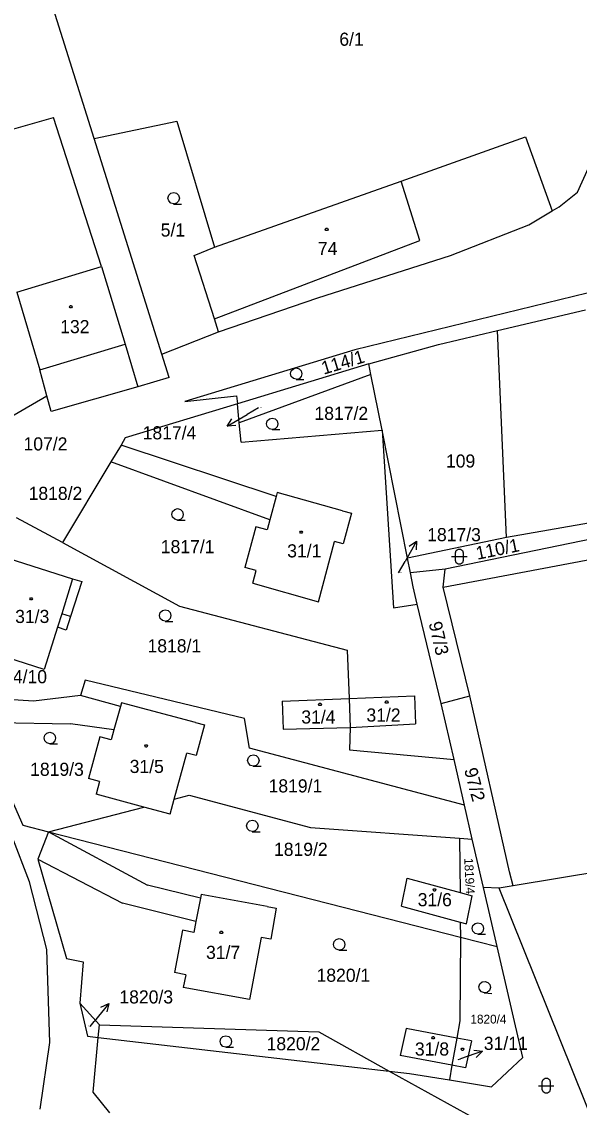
# Model space of a CAD drawing. Extents: x -799786 to -795190, y -1021716 to -1017834.
# Drawn here: x -797930.9 to -797858.7, y -1019054.3 to -1018913.6 of the extents above; entities that cross this region are included whole.
import ezdxf

# ---------------------------------------------------------------- set-up
doc = ezdxf.new("R2010")
doc.units = 0
for name, color, linetype in [('Default', 7, 'Continuous'), ('KN_HRANICE', 7, 'Continuous'), ('KN_KULTURY', 7, 'Continuous'), ('KN_PARCELY', 7, 'Continuous'), ('KN_SLUCKY', 7, 'Continuous')]:
    doc.layers.add(name, color=color, linetype=linetype)

# ---------------------------------------------------------------- blocks, each defined once
blk = doc.blocks.new('304')
at = {"layer": 'Default'}
blk.add_lwpolyline([(0, 0), (-0.38, 0.1), (-0.65, 0.37), (-0.75, 0.74), (-0.65, 1.11), (-0.38, 1.38), (-0.01, 1.48), (0.36, 1.38), (0.63, 1.11), (0.73, 0.73), (0.63, 0.35), (0.36, 0.08), (-0.02, -0.02), (0.98, -0.02)], dxfattribs=at)
blk = doc.blocks.new('316')
at = {"layer": 'Default'}
for points in [[(-0.5, 1.5), (-0.4, 1.79), (-0.15, 1.97), (0.16, 1.97), (0.41, 1.79), (0.51, 1.5), (0.51, 0.5), (0.41, 0.21), (0.16, 0.03), (-0.15, 0.03), (-0.4, 0.21), (-0.5, 0.5), (-0.5, 1.5)], [(-1, 1), (0.27, 1), (1, 1)]]:
    blk.add_lwpolyline(points, dxfattribs=at)
blk = doc.blocks.new('10292')
at = {"layer": 'Default'}
blk.add_line((0, 3), (0, 0), dxfattribs=at)
blk.add_lwpolyline([(-0.5, 2), (0, 3), (0.5, 2)], dxfattribs=at)
blk = doc.blocks.new('402')
at = {"layer": 'Default'}
blk.add_lwpolyline([(0.09, 0.15), (0.18, 0), (0.09, -0.15), (-0.09, -0.15), (-0.18, 0), (-0.09, 0.15), (0.09, 0.15)], dxfattribs=at)

msp = doc.modelspace()

# ---------------------------------------------------------------- linework, layer by layer
at = {"layer": 'KN_HRANICE'}
for p, q in [((-797921.5, -1018928.71), (-797931.74, -1018896.06)), ((-797936.24, -1018928.69), (-797926.78, -1018925.98)), ((-797920.53, -1018945.32), (-797926.78, -1018925.98)), ((-797921.5, -1018928.71), (-797910.8, -1018926.48)), ((-797910.8, -1018926.48), (-797905.9, -1018942.82)), ((-797912.72, -1018956.68), (-797921.5, -1018928.71)), ((-797881.76, -1018934.25), (-797865.66, -1018928.52)), ((-797865.66, -1018928.52), (-797862.2, -1018938.11)), ((-797858.91, -1018935.69), (-797856.04, -1018929.36)), ((-797905.9, -1018942.82), (-797881.76, -1018934.25)), ((-797908.54, -1018943.89), (-797905.9, -1018942.82)), ((-797905.93, -1018952.07), (-797908.54, -1018943.89)), ((-797920.53, -1018945.32), (-797917.5, -1018955.39)), ((-797931.53, -1018948.65), (-797928.55, -1018958.72)), ((-797855.89, -1018948.34), (-797887.74, -1018956.13)), ((-797869.28, -1018953.62), (-797857.87, -1018950.94)), ((-797905.4, -1018953.76), (-797905.93, -1018952.07)), ((-797912.72, -1018956.68), (-797905.4, -1018953.76)), ((-797876.92, -1018955.41), (-797869.28, -1018953.62)), ((-797868.08, -1018980.41), (-797869.28, -1018953.62)), ((-797917.5, -1018955.39), (-797915.84, -1018960.89)), ((-797887.74, -1018956.13), (-797909.74, -1018962.8)), ((-797885.92, -1018957.93), (-797876.92, -1018955.41)), ((-797911.78, -1018959.68), (-797912.72, -1018956.68)), ((-797927.62, -1018962.07), (-797928.55, -1018958.72)), ((-797885.92, -1018957.93), (-797902.94, -1018963.09)), ((-797885.65, -1018959.3), (-797885.92, -1018957.93)), ((-797911.78, -1018959.68), (-797915.84, -1018960.89)), ((-797885.65, -1018959.3), (-797902.7, -1018965.57)), ((-797884.22, -1018966.52), (-797885.65, -1018959.3)), ((-797915.84, -1018960.89), (-797927.05, -1018964.12)), ((-797935.14, -1018966.41), (-797927.62, -1018962.07)), ((-797927.05, -1018964.12), (-797927.62, -1018962.07)), ((-797902.94, -1018963.09), (-797917.5, -1018967.51)), ((-797909.74, -1018962.8), (-797903.08, -1018962.08)), ((-797903.08, -1018962.08), (-797902.94, -1018963.09)), ((-797902.7, -1018965.57), (-797902.94, -1018963.09)), ((-797902.45, -1018968.07), (-797902.7, -1018965.57)), ((-797902.45, -1018968.07), (-797884.22, -1018966.52)), ((-797884.22, -1018966.52), (-797882.75, -1018989.54)), ((-797880.92, -1018983.12), (-797884.22, -1018966.52)), ((-797917.99, -1018968.46), (-797919.35, -1018970.64)), ((-797917.5, -1018967.51), (-797917.99, -1018968.46)), ((-797897.94, -1018975.1), (-797917.99, -1018968.46)), ((-797919.35, -1018970.64), (-797925.6, -1018981.08)), ((-797898.76, -1018978.15), (-797919.35, -1018970.64)), ((-797897.81, -1018974.62), (-797897.94, -1018975.1)), ((-797889.34, -1018976.96), (-797897.81, -1018974.62)), ((-797889.34, -1018976.96), (-797888.17, -1018977.28)), ((-797925.6, -1018981.08), (-797931.55, -1018977.89)), ((-797898.76, -1018978.15), (-797899.11, -1018979.45)), ((-797888.17, -1018977.28), (-797889.26, -1018981.23)), ((-797876.31, -1018986.88), (-797829.82, -1018978.1)), ((-797851.15, -1018977.47), (-797868.08, -1018980.41)), ((-797900.56, -1018979.06), (-797901.97, -1018984.32)), ((-797899.11, -1018979.45), (-797900.56, -1018979.06)), ((-797848.43, -1018978.83), (-797876.06, -1018984.55)), ((-797925.6, -1018981.08), (-797910.44, -1018989.33)), ((-797892.44, -1018988.78), (-797890.38, -1018980.93)), ((-797889.26, -1018981.23), (-797890.38, -1018980.93)), ((-797868.08, -1018980.41), (-797880.92, -1018983.12)), ((-797932.67, -1018983.1), (-797924.31, -1018985.78)), ((-797880.54, -1018985.03), (-797880.92, -1018983.12)), ((-797900.52, -1018984.71), (-797901.97, -1018984.32)), ((-797900.96, -1018986.35), (-797900.52, -1018984.71)), ((-797876.06, -1018984.55), (-797880.54, -1018985.03)), ((-797880.18, -1018986.82), (-797880.54, -1018985.03)), ((-797876.31, -1018986.88), (-797876.06, -1018984.55)), ((-797923.11, -1018986.14), (-797924.57, -1018990.67)), ((-797924.31, -1018985.78), (-797923.11, -1018986.14)), ((-797900.96, -1018986.35), (-797892.44, -1018988.78)), ((-797879.65, -1018989.07), (-797880.18, -1018986.82)), ((-797872.85, -1019000.96), (-797876.31, -1018986.88)), ((-797910.44, -1018989.33), (-797888.73, -1018995.05)), ((-797882.75, -1018989.54), (-797879.65, -1018989.07)), ((-797876.54, -1019001.93), (-797879.65, -1018989.07)), ((-797924.57, -1018990.67), (-797925.13, -1018992.42)), ((-797926.26, -1018992.05), (-797927.99, -1018997.54)), ((-797925.13, -1018992.42), (-797926.26, -1018992.05)), ((-797927.99, -1018997.54), (-797936.46, -1018994.83)), ((-797888.73, -1018995.05), (-797888.49, -1019001.31)), ((-797922.68, -1018998.9), (-797923.27, -1019000.91)), ((-797902.02, -1019003.87), (-797922.68, -1018998.9)), ((-797923.27, -1019000.91), (-797929.37, -1019001.64)), ((-797918.11, -1019002.32), (-797923.27, -1019000.91)), ((-797888.49, -1019001.31), (-797880, -1019000.96)), ((-797880, -1019000.96), (-797879.88, -1019004.56)), ((-797876.54, -1019001.93), (-797872.85, -1019000.96)), ((-797867.69, -1019023.75), (-797872.85, -1019000.96)), ((-797929.37, -1019001.64), (-797935.97, -1019001.2)), ((-797917.98, -1019001.84), (-797918.11, -1019002.32)), ((-797908.39, -1019004.42), (-797917.98, -1019001.84)), ((-797897.14, -1019001.66), (-797888.49, -1019001.31)), ((-797897.14, -1019001.66), (-797897.02, -1019005.26)), ((-797888.49, -1019001.31), (-797888.34, -1019005.04)), ((-797874.87, -1019009.21), (-797876.54, -1019001.93)), ((-797901.4, -1019007.72), (-797902.02, -1019003.87)), ((-797936.37, -1019004.37), (-797924.56, -1019004.56)), ((-797918.95, -1019005.36), (-797924.56, -1019004.56)), ((-797918.95, -1019005.36), (-797919.31, -1019006.66)), ((-797908.39, -1019004.42), (-797907.23, -1019004.73)), ((-797907.23, -1019004.73), (-797908.3, -1019008.69)), ((-797897.02, -1019005.26), (-797888.34, -1019005.04)), ((-797888.34, -1019005.04), (-797888.43, -1019007.97)), ((-797888.34, -1019005.04), (-797879.88, -1019004.56)), ((-797920.76, -1019006.26), (-797922.25, -1019011.67)), ((-797919.31, -1019006.66), (-797920.76, -1019006.26)), ((-797873.56, -1019015.1), (-797901.4, -1019007.72)), ((-797888.43, -1019007.97), (-797874.87, -1019009.21)), ((-797911.13, -1019014.35), (-797909.48, -1019008.37)), ((-797908.3, -1019008.69), (-797909.48, -1019008.37)), ((-797873.56, -1019015.1), (-797874.87, -1019009.21)), ((-797920.81, -1019012.07), (-797922.25, -1019011.67)), ((-797920.81, -1019012.07), (-797921.26, -1019013.71)), ((-797915.07, -1019015.38), (-797921.26, -1019013.71)), ((-797932.1, -1019014.57), (-797930.74, -1019017.71)), ((-797911.67, -1019016.29), (-797911.13, -1019014.35)), ((-797911.13, -1019014.35), (-797909.18, -1019013.84)), ((-797909.18, -1019013.84), (-797893.47, -1019018.01)), ((-797872.54, -1019019.52), (-797873.56, -1019015.1)), ((-797927.43, -1019018.59), (-797915.07, -1019015.38)), ((-797911.67, -1019016.29), (-797915.07, -1019015.38)), ((-797930.74, -1019017.71), (-797927.43, -1019018.59)), ((-797893.47, -1019018.01), (-797874.18, -1019019.4)), ((-797929.89, -1019025.05), (-797932.14, -1019019.09)), ((-797927.43, -1019018.59), (-797928.79, -1019022.1)), ((-797927.43, -1019018.59), (-797914.6, -1019025.49)), ((-797927.43, -1019018.59), (-797874.06, -1019032.21)), ((-797874.18, -1019019.4), (-797872.54, -1019019.52)), ((-797874.18, -1019019.4), (-797874.12, -1019026.43)), ((-797826.24, -1019018.74), (-797867.23, -1019025.59)), ((-797871.08, -1019025.81), (-797872.54, -1019019.52)), ((-797928.79, -1019022.1), (-797917.85, -1019027.83)), ((-797928.79, -1019022.1), (-797925.1, -1019034.98)), ((-797927.63, -1019033.84), (-797929.89, -1019025.05)), ((-797881.7, -1019028.21), (-797880.96, -1019024.58)), ((-797880.96, -1019024.58), (-797874.12, -1019026.43)), ((-797867.23, -1019025.59), (-797867.69, -1019023.75)), ((-797907.74, -1019027.19), (-797914.6, -1019025.49)), ((-797874.12, -1019026.43), (-797872.56, -1019026.85)), ((-797869.31, -1019033.42), (-797871.08, -1019025.81)), ((-797869.05, -1019025.87), (-797871.08, -1019025.81)), ((-797867.23, -1019025.59), (-797869.05, -1019025.87)), ((-797852.67, -1019066.58), (-797869.05, -1019025.87)), ((-797908.32, -1019030.19), (-797917.85, -1019027.83)), ((-797907.65, -1019026.7), (-797907.74, -1019027.19)), ((-797899.09, -1019028.25), (-797907.65, -1019026.7)), ((-797873.3, -1019030.48), (-797872.56, -1019026.85)), ((-797899.09, -1019028.25), (-797897.91, -1019028.46)), ((-797897.91, -1019028.46), (-797898.64, -1019032.5)), ((-797881.7, -1019028.21), (-797874.08, -1019030.27)), ((-797908.32, -1019030.19), (-797908.59, -1019031.61)), ((-797874.08, -1019030.27), (-797874.06, -1019032.21)), ((-797874.08, -1019030.27), (-797873.3, -1019030.48)), ((-797910.06, -1019031.33), (-797911.11, -1019036.81)), ((-797908.59, -1019031.61), (-797910.06, -1019031.33)), ((-797899.86, -1019032.28), (-797901.4, -1019040.31)), ((-797898.64, -1019032.5), (-797899.86, -1019032.28)), ((-797874.06, -1019032.21), (-797874.14, -1019043.07)), ((-797874.06, -1019032.21), (-797869.31, -1019033.42)), ((-797865.97, -1019047.84), (-797869.31, -1019033.42)), ((-797927.24, -1019045.89), (-797927.63, -1019033.84)), ((-797925.1, -1019034.98), (-797922.91, -1019035.41)), ((-797922.91, -1019035.41), (-797923.37, -1019040.79)), ((-797909.64, -1019037.09), (-797911.11, -1019036.81)), ((-797909.64, -1019037.09), (-797909.96, -1019038.76)), ((-797901.4, -1019040.31), (-797909.96, -1019038.76)), ((-797923.37, -1019040.79), (-797922.38, -1019045.06)), ((-797923.37, -1019040.79), (-797920.79, -1019043.61)), ((-797874.14, -1019043.07), (-797874.54, -1019045.32)), ((-797920.99, -1019045.22), (-797920.79, -1019043.61)), ((-797920.79, -1019043.61), (-797892.41, -1019044.51)), ((-797892.41, -1019044.51), (-797883.29, -1019049.58)), ((-797881.11, -1019044.08), (-797881.85, -1019047.56)), ((-797874.54, -1019045.32), (-797881.11, -1019044.08)), ((-797928.48, -1019054.53), (-797927.24, -1019045.89)), ((-797922.38, -1019045.06), (-797920.99, -1019045.22)), ((-797921.61, -1019052.33), (-797920.99, -1019045.22)), ((-797920.99, -1019045.22), (-797883.29, -1019049.58)), ((-797874.54, -1019045.32), (-797875.16, -1019048.83)), ((-797872.65, -1019045.68), (-797874.54, -1019045.32)), ((-797872.65, -1019045.68), (-797873.39, -1019049.16)), ((-797875.16, -1019048.83), (-797881.85, -1019047.56)), ((-797875.16, -1019048.83), (-797875.49, -1019050.72)), ((-797873.39, -1019049.16), (-797875.16, -1019048.83)), ((-797870.04, -1019051.61), (-797865.97, -1019047.84)), ((-797883.29, -1019049.58), (-797880.65, -1019049.88)), ((-797883.29, -1019049.58), (-797872.02, -1019055.83)), ((-797880.65, -1019049.88), (-797875.49, -1019050.72)), ((-797875.49, -1019050.72), (-797870.04, -1019051.61)), ((-797919.48, -1019055.01), (-797921.61, -1019052.33))]:
    msp.add_line(p, q, dxfattribs=at)
for points in [[(-797862.2, -1018938.11), (-797861.27, -1018937.56), (-797858.91, -1018935.69)], [(-797905.4, -1018953.76), (-797892.54, -1018949.37), (-797875.35, -1018943.87), (-797865.2, -1018939.9), (-797862.2, -1018938.11)]]:
    msp.add_lwpolyline(points, dxfattribs=at)
at = {"layer": 'KN_PARCELY'}
for p, q in [((-797900.22, -1018963.61), (-797901.69, -1018964.48)), ((-797882.1, -1018985.02), (-797881.24, -1018983.52)), ((-797922.03, -1019043.79), (-797921.51, -1019043.15)), ((-797874.35, -1019048.1), (-797874.06, -1019048))]:
    msp.add_line(p, q, dxfattribs=at)
at = {"layer": 'KN_SLUCKY'}
for p, q in [((-797879.31, -1018941.92), (-797881.76, -1018934.25)), ((-797905.93, -1018952.07), (-797879.31, -1018941.92)), ((-797931.53, -1018948.65), (-797920.53, -1018945.32)), ((-797928.55, -1018958.72), (-797917.5, -1018955.39)), ((-797897.94, -1018975.1), (-797898.76, -1018978.15)), ((-797924.31, -1018985.78), (-797925.7, -1018990.31)), ((-797925.7, -1018990.31), (-797926.26, -1018992.05)), ((-797924.57, -1018990.67), (-797925.7, -1018990.31)), ((-797918.11, -1019002.32), (-797918.95, -1019005.36)), ((-797907.74, -1019027.19), (-797908.32, -1019030.19))]:
    msp.add_line(p, q, dxfattribs=at)

# ---------------------------------------------------------------- block references
at = {"layer": 'KN_KULTURY'}
for name, p in [('304', (-797911.19, -1018937.19)), ('402', (-797891.39, -1018940.5)), ('402', (-797924.53, -1018950.52)), ('304', (-797895.32, -1018959.93)), ('304', (-797898.43, -1018966.43)), ('304', (-797910.69, -1018978.17)), ('402', (-797894.69, -1018979.74)), ('316', (-797874.21, -1018983.91)), ('402', (-797929.67, -1018988.38)), ('304', (-797912.29, -1018991.28)), ('402', (-797892.25, -1019002.06)), ('402', (-797883.62, -1019001.75)), ('304', (-797927.23, -1019007.15)), ('402', (-797914.77, -1019007.45)), ('304', (-797900.87, -1019010.06)), ('304', (-797901, -1019018.54)), ('402', (-797877.42, -1019026.11)), ('304', (-797871.79, -1019031.84)), ('402', (-797905.03, -1019031.62)), ('304', (-797889.76, -1019033.9)), ('304', (-797904.44, -1019046.48)), ('402', (-797877.59, -1019045.27)), ('402', (-797873.79, -1019046.76)), ('316', (-797862.96, -1019052.48))]:
    msp.add_blockref(name, p, dxfattribs=at)
at = {"layer": 'KN_KULTURY', "rotation": -4.1932089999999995}
msp.add_blockref('304', (-797870.97, -1019039.44), dxfattribs=at)
at = {"layer": 'KN_PARCELY'}
for p, rotation in [((-797901.69, -1018964.48), 120.66491200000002), ((-797881.24, -1018983.52), -29.632535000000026), ((-797921.51, -1019043.15), -39.02904300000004), ((-797874.06, -1019048), -70.77090499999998)]:
    msp.add_blockref('10292', p, dxfattribs=dict(at, rotation=rotation))

# ---------------------------------------------------------------- texts
for s, height, p in [('6/1', 1.7, (-797889.75, -1018916.7)), ('5/1', 1.7, (-797912.88, -1018941.43)), ('74', 1.7, (-797892.53, -1018943.83)), ('132', 1.7, (-797925.9, -1018953.95)), ('1817/4', 0.1, (-797900.2, -1018963.61)), ('1817/2', 1.7, (-797892.97, -1018965.19)), ('1817/4', 1.7, (-797915.22, -1018967.71)), ('107/2', 1.7, (-797930.65, -1018969.15)), ('109', 1.7, (-797875.94, -1018971.37)), ('1818/2', 1.7, (-797929.99, -1018975.56)), ('1817/3', 1.7, (-797878.37, -1018980.91)), ('1817/1', 1.7, (-797912.87, -1018982.47)), ('31/1', 1.7, (-797896.5, -1018983.01)), ('1817/3', 0.1, (-797882.08, -1018985.02)), ('31/3', 1.7, (-797931.73, -1018991.51)), ('1818/1', 1.7, (-797914.59, -1018995.32)), ('1744/10', 1.7, (-797935.82, -1018999.32)), ('31/2', 1.7, (-797886.24, -1019004.29)), ('31/4', 1.7, (-797894.67, -1019004.54)), ('1819/3', 1.7, (-797929.79, -1019011.32)), ('31/5', 1.7, (-797916.9, -1019010.95)), ('1819/1', 1.7, (-797898.91, -1019013.47)), ('1819/2', 1.7, (-797898.21, -1019021.69)), ('31/6', 1.7, (-797879.6, -1019028.22)), ('31/7', 1.7, (-797907.01, -1019035.05)), ('1820/1', 1.7, (-797892.7, -1019038.01)), ('1820/3', 1.7, (-797918.23, -1019040.82)), ('1820/4', 1.14, (-797872.77, -1019043.42)), ('1820/3', 0.1, (-797922.33, -1019043.79)), ('1820/2', 1.7, (-797899.17, -1019046.89)), ('31/8', 1.7, (-797879.96, -1019047.57)), ('31/11', 1.7, (-797871.04, -1019046.84)), ('31/11', 0.1, (-797874.34, -1019048.1))]:
    msp.add_text(s, height=height, dxfattribs=at).set_placement(p)
for s, height, rotation, p in [('114/1', 1.7, 16.73, (-797891.78, -1018959.34)), ('110/1', 1.7, 11.516, (-797871.88, -1018983.33)), ('97/3', 1.7, 282.984, (-797878.19, -1018991.53)), ('97/2', 1.7, 284.703, (-797873.6, -1019010.52)), ('1819/4', 1.14, 273.014, (-797873.58, -1019022))]:
    msp.add_text(s, height=height, rotation=rotation, dxfattribs=at).set_placement(p)

doc.saveas('drawing.dxf')
